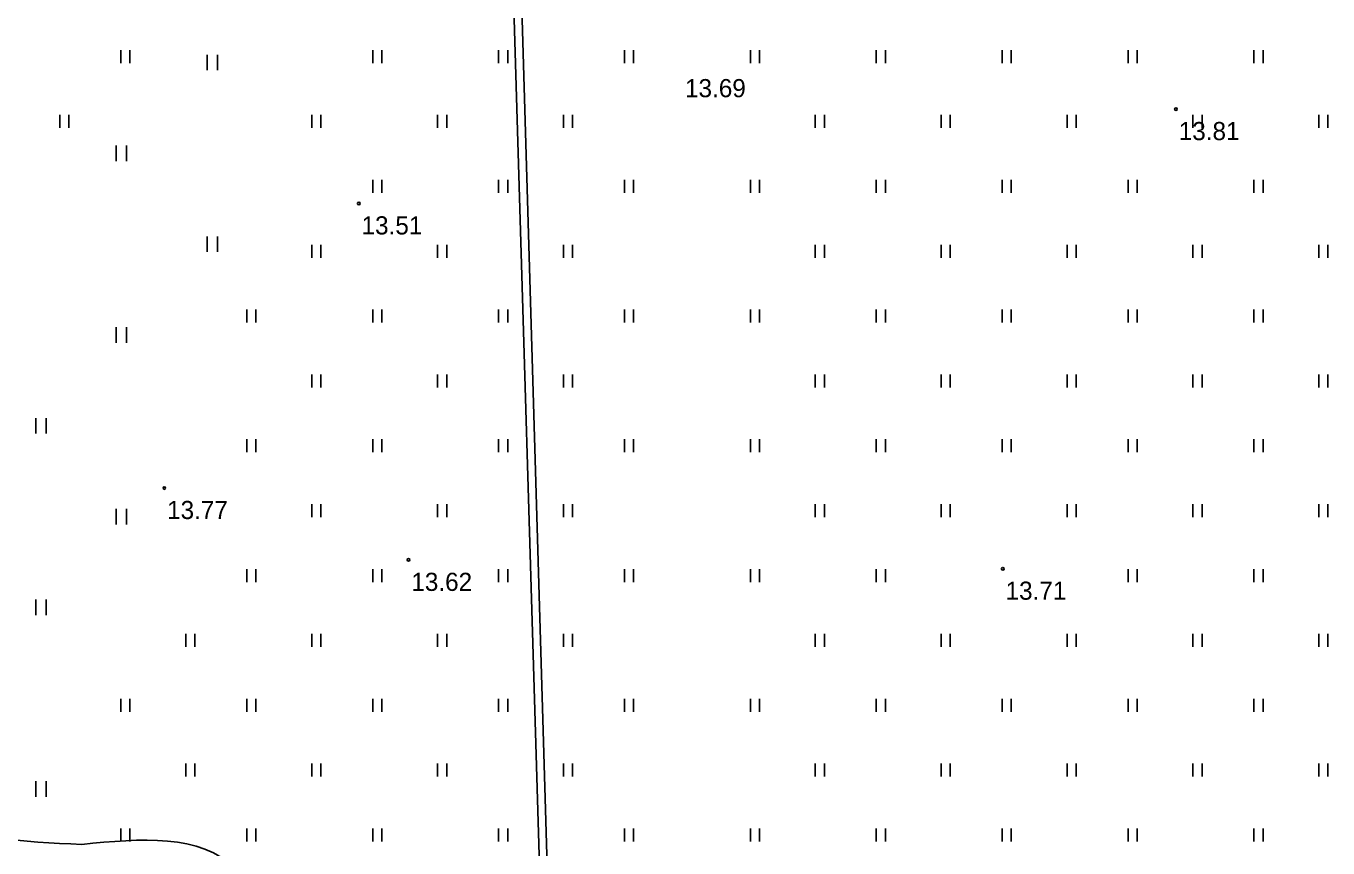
# Model space of a CAD drawing. Extents: x 503877 to 504025, y 304562 to 304725.
# Drawn here: x 503974.7 to 504024.9, y 304658.7 to 304690.4 of the extents above; entities that cross this region are included whole.
import ezdxf

# ---------------------------------------------------------------- set-up
doc = ezdxf.new("R2010")
doc.units = 0
for name, color, linetype in [('CELI_CMAL_####_####_#', 7, 'Continuous'), ('RELJ_AATZ_####_TKST_#', 7, 'Continuous'), ('RELJ_ELEM_####_####_#', 7, 'Continuous'), ('RELJ_HORZ_PAMT_####_#', 7, 'Continuous'), ('SAKT_VADP_KABE_####_#', 7, 'Continuous'), ('TERT_ELEM_####_####_#', 7, 'Continuous')]:
    doc.layers.add(name, color=color, linetype=linetype)

msp = doc.modelspace()

# ---------------------------------------------------------------- linework, layer by layer
at = {"layer": 'CELI_CMAL_####_####_#'}
msp.add_spline([(503958.742, 304680.69), (503969.414, 304697.055), (503975.45, 304710.561), (503980.58, 304721.12)], degree=3, dxfattribs=at)
at = {"layer": 'RELJ_ELEM_####_####_#'}
for centre in [(504019.004, 304687.166), (503987.523, 304683.531), (503980.032, 304672.563), (503989.441, 304669.793), (504012.333, 304669.452)]:
    msp.add_circle(centre, 0.05, dxfattribs=at)
at = {"layer": 'RELJ_HORZ_PAMT_####_#'}
for points in [[(503976.857, 304658.83), (503971.294, 304660.253), (503970.34, 304666.569), (503970.027, 304667.82)], [(503987.539, 304625.902), (503985.892, 304637.275), (503983.106, 304645.98), (503983.425, 304657.056), (503982.792, 304657.882), (503976.857, 304658.83)]]:
    msp.add_spline(points, degree=3, dxfattribs=at)
at = {"layer": 'SAKT_VADP_KABE_####_#'}
for p, q in [((503993.253, 304709.476), (503996.275, 304607.968)), ((503992.977, 304708.659), (503995.977, 304607.917))]:
    msp.add_line(p, q, dxfattribs=at)
at = {"layer": 'TERT_ELEM_####_####_#'}
for p, q in [((503978.36, 304688.941), (503978.36, 304689.441)), ((503978.71, 304688.941), (503978.71, 304689.441)), ((503981.679, 304688.662), (503981.679, 304689.262)), ((503982.079, 304688.662), (503982.079, 304689.262)), ((503988.06, 304688.941), (503988.06, 304689.441)), ((503988.41, 304688.941), (503988.41, 304689.441)), ((503992.91, 304688.941), (503992.91, 304689.441)), ((503993.26, 304688.941), (503993.26, 304689.441)), ((503997.76, 304688.941), (503997.76, 304689.441)), ((503998.11, 304688.941), (503998.11, 304689.441)), ((504002.61, 304688.941), (504002.61, 304689.441)), ((504002.96, 304688.941), (504002.96, 304689.441)), ((504007.46, 304688.941), (504007.46, 304689.441)), ((504007.81, 304688.941), (504007.81, 304689.441)), ((504012.31, 304688.941), (504012.31, 304689.441)), ((504012.66, 304688.941), (504012.66, 304689.441)), ((504017.16, 304688.941), (504017.16, 304689.441)), ((504017.51, 304688.941), (504017.51, 304689.441)), ((504022.01, 304688.941), (504022.01, 304689.441)), ((504022.36, 304688.941), (504022.36, 304689.441)), ((503976.01, 304686.441), (503976.01, 304686.941)), ((503976.36, 304686.441), (503976.36, 304686.941)), ((503985.71, 304686.441), (503985.71, 304686.941)), ((503986.06, 304686.441), (503986.06, 304686.941)), ((503990.56, 304686.441), (503990.56, 304686.941)), ((503990.91, 304686.441), (503990.91, 304686.941)), ((503995.41, 304686.441), (503995.41, 304686.941)), ((503995.76, 304686.441), (503995.76, 304686.941)), ((504005.11, 304686.441), (504005.11, 304686.941)), ((504005.46, 304686.441), (504005.46, 304686.941)), ((504009.96, 304686.441), (504009.96, 304686.941)), ((504010.31, 304686.441), (504010.31, 304686.941)), ((504014.81, 304686.441), (504014.81, 304686.941)), ((504015.16, 304686.441), (504015.16, 304686.941)), ((504019.66, 304686.441), (504019.66, 304686.941)), ((504020.01, 304686.441), (504020.01, 304686.941)), ((504024.51, 304686.441), (504024.51, 304686.941)), ((504024.86, 304686.441), (504024.86, 304686.941)), ((503978.179, 304685.162), (503978.179, 304685.762)), ((503978.579, 304685.162), (503978.579, 304685.762)), ((503988.06, 304683.941), (503988.06, 304684.441)), ((503988.41, 304683.941), (503988.41, 304684.441)), ((503992.91, 304683.941), (503992.91, 304684.441)), ((503993.26, 304683.941), (503993.26, 304684.441)), ((503997.76, 304683.941), (503997.76, 304684.441)), ((503998.11, 304683.941), (503998.11, 304684.441)), ((504002.61, 304683.941), (504002.61, 304684.441)), ((504002.96, 304683.941), (504002.96, 304684.441)), ((504007.46, 304683.941), (504007.46, 304684.441)), ((504007.81, 304683.941), (504007.81, 304684.441)), ((504012.31, 304683.941), (504012.31, 304684.441)), ((504012.66, 304683.941), (504012.66, 304684.441)), ((504017.16, 304683.941), (504017.16, 304684.441)), ((504017.51, 304683.941), (504017.51, 304684.441)), ((504022.01, 304683.941), (504022.01, 304684.441)), ((504022.36, 304683.941), (504022.36, 304684.441)), ((503981.679, 304681.662), (503981.679, 304682.262)), ((503982.079, 304681.662), (503982.079, 304682.262)), ((503985.71, 304681.441), (503985.71, 304681.941)), ((503986.06, 304681.441), (503986.06, 304681.941)), ((503990.56, 304681.441), (503990.56, 304681.941)), ((503990.91, 304681.441), (503990.91, 304681.941)), ((503995.41, 304681.441), (503995.41, 304681.941)), ((503995.76, 304681.441), (503995.76, 304681.941)), ((504005.11, 304681.441), (504005.11, 304681.941)), ((504005.46, 304681.441), (504005.46, 304681.941)), ((504009.96, 304681.441), (504009.96, 304681.941)), ((504010.31, 304681.441), (504010.31, 304681.941)), ((504014.81, 304681.441), (504014.81, 304681.941)), ((504015.16, 304681.441), (504015.16, 304681.941)), ((504019.66, 304681.441), (504019.66, 304681.941)), ((504020.01, 304681.441), (504020.01, 304681.941)), ((504024.51, 304681.441), (504024.51, 304681.941)), ((504024.86, 304681.441), (504024.86, 304681.941)), ((503983.21, 304678.941), (503983.21, 304679.441)), ((503983.56, 304678.941), (503983.56, 304679.441)), ((503988.06, 304678.941), (503988.06, 304679.441)), ((503988.41, 304678.941), (503988.41, 304679.441)), ((503992.91, 304678.941), (503992.91, 304679.441)), ((503993.26, 304678.941), (503993.26, 304679.441)), ((503997.76, 304678.941), (503997.76, 304679.441)), ((503998.11, 304678.941), (503998.11, 304679.441)), ((504002.61, 304678.941), (504002.61, 304679.441)), ((504002.96, 304678.941), (504002.96, 304679.441)), ((504007.46, 304678.941), (504007.46, 304679.441)), ((504007.81, 304678.941), (504007.81, 304679.441)), ((504012.31, 304678.941), (504012.31, 304679.441)), ((504012.66, 304678.941), (504012.66, 304679.441)), ((504017.16, 304678.941), (504017.16, 304679.441)), ((504017.51, 304678.941), (504017.51, 304679.441)), ((504022.01, 304678.941), (504022.01, 304679.441)), ((504022.36, 304678.941), (504022.36, 304679.441)), ((503978.179, 304678.162), (503978.179, 304678.762)), ((503978.579, 304678.162), (503978.579, 304678.762)), ((503985.71, 304676.441), (503985.71, 304676.941)), ((503986.06, 304676.441), (503986.06, 304676.941)), ((503990.56, 304676.441), (503990.56, 304676.941)), ((503990.91, 304676.441), (503990.91, 304676.941)), ((503995.41, 304676.441), (503995.41, 304676.941)), ((503995.76, 304676.441), (503995.76, 304676.941)), ((504005.11, 304676.441), (504005.11, 304676.941)), ((504005.46, 304676.441), (504005.46, 304676.941)), ((504009.96, 304676.441), (504009.96, 304676.941)), ((504010.31, 304676.441), (504010.31, 304676.941)), ((504014.81, 304676.441), (504014.81, 304676.941)), ((504015.16, 304676.441), (504015.16, 304676.941)), ((504019.66, 304676.441), (504019.66, 304676.941)), ((504020.01, 304676.441), (504020.01, 304676.941)), ((504024.51, 304676.441), (504024.51, 304676.941)), ((504024.86, 304676.441), (504024.86, 304676.941)), ((503975.079, 304674.662), (503975.079, 304675.262)), ((503975.479, 304674.662), (503975.479, 304675.262)), ((503983.21, 304673.941), (503983.21, 304674.441)), ((503983.56, 304673.941), (503983.56, 304674.441)), ((503988.06, 304673.941), (503988.06, 304674.441)), ((503988.41, 304673.941), (503988.41, 304674.441)), ((503992.91, 304673.941), (503992.91, 304674.441)), ((503993.26, 304673.941), (503993.26, 304674.441)), ((503997.76, 304673.941), (503997.76, 304674.441)), ((503998.11, 304673.941), (503998.11, 304674.441)), ((504002.61, 304673.941), (504002.61, 304674.441)), ((504002.96, 304673.941), (504002.96, 304674.441)), ((504007.46, 304673.941), (504007.46, 304674.441)), ((504007.81, 304673.941), (504007.81, 304674.441)), ((504012.31, 304673.941), (504012.31, 304674.441)), ((504012.66, 304673.941), (504012.66, 304674.441)), ((504017.16, 304673.941), (504017.16, 304674.441)), ((504017.51, 304673.941), (504017.51, 304674.441)), ((504022.01, 304673.941), (504022.01, 304674.441)), ((504022.36, 304673.941), (504022.36, 304674.441)), ((503978.179, 304671.162), (503978.179, 304671.762)), ((503978.579, 304671.162), (503978.579, 304671.762)), ((503985.71, 304671.441), (503985.71, 304671.941)), ((503986.06, 304671.441), (503986.06, 304671.941)), ((503990.56, 304671.441), (503990.56, 304671.941)), ((503990.91, 304671.441), (503990.91, 304671.941)), ((503995.41, 304671.441), (503995.41, 304671.941)), ((503995.76, 304671.441), (503995.76, 304671.941)), ((504005.11, 304671.441), (504005.11, 304671.941)), ((504005.46, 304671.441), (504005.46, 304671.941)), ((504009.96, 304671.441), (504009.96, 304671.941)), ((504010.31, 304671.441), (504010.31, 304671.941)), ((504014.81, 304671.441), (504014.81, 304671.941)), ((504015.16, 304671.441), (504015.16, 304671.941)), ((504019.66, 304671.441), (504019.66, 304671.941)), ((504020.01, 304671.441), (504020.01, 304671.941)), ((504024.51, 304671.441), (504024.51, 304671.941)), ((504024.86, 304671.441), (504024.86, 304671.941)), ((503983.21, 304668.941), (503983.21, 304669.441)), ((503983.56, 304668.941), (503983.56, 304669.441)), ((503988.06, 304668.941), (503988.06, 304669.441)), ((503988.41, 304668.941), (503988.41, 304669.441)), ((503992.91, 304668.941), (503992.91, 304669.441)), ((503993.26, 304668.941), (503993.26, 304669.441)), ((503997.76, 304668.941), (503997.76, 304669.441)), ((503998.11, 304668.941), (503998.11, 304669.441)), ((504002.61, 304668.941), (504002.61, 304669.441)), ((504002.96, 304668.941), (504002.96, 304669.441)), ((504007.46, 304668.941), (504007.46, 304669.441)), ((504007.81, 304668.941), (504007.81, 304669.441)), ((504017.16, 304668.941), (504017.16, 304669.441)), ((504017.51, 304668.941), (504017.51, 304669.441)), ((504022.01, 304668.941), (504022.01, 304669.441)), ((504022.36, 304668.941), (504022.36, 304669.441)), ((503975.079, 304667.662), (503975.079, 304668.262)), ((503975.479, 304667.662), (503975.479, 304668.262)), ((503980.86, 304666.441), (503980.86, 304666.941)), ((503981.21, 304666.441), (503981.21, 304666.941)), ((503985.71, 304666.441), (503985.71, 304666.941)), ((503986.06, 304666.441), (503986.06, 304666.941)), ((503990.56, 304666.441), (503990.56, 304666.941)), ((503990.91, 304666.441), (503990.91, 304666.941)), ((503995.41, 304666.441), (503995.41, 304666.941)), ((503995.76, 304666.441), (503995.76, 304666.941)), ((504005.11, 304666.441), (504005.11, 304666.941)), ((504005.46, 304666.441), (504005.46, 304666.941)), ((504009.96, 304666.441), (504009.96, 304666.941)), ((504010.31, 304666.441), (504010.31, 304666.941)), ((504014.81, 304666.441), (504014.81, 304666.941)), ((504015.16, 304666.441), (504015.16, 304666.941)), ((504019.66, 304666.441), (504019.66, 304666.941)), ((504020.01, 304666.441), (504020.01, 304666.941)), ((504024.51, 304666.441), (504024.51, 304666.941)), ((504024.86, 304666.441), (504024.86, 304666.941)), ((503978.36, 304663.941), (503978.36, 304664.441)), ((503978.71, 304663.941), (503978.71, 304664.441)), ((503983.21, 304663.941), (503983.21, 304664.441)), ((503983.56, 304663.941), (503983.56, 304664.441)), ((503988.06, 304663.941), (503988.06, 304664.441)), ((503988.41, 304663.941), (503988.41, 304664.441)), ((503992.91, 304663.941), (503992.91, 304664.441)), ((503993.26, 304663.941), (503993.26, 304664.441)), ((503997.76, 304663.941), (503997.76, 304664.441)), ((503998.11, 304663.941), (503998.11, 304664.441)), ((504002.61, 304663.941), (504002.61, 304664.441)), ((504002.96, 304663.941), (504002.96, 304664.441)), ((504007.46, 304663.941), (504007.46, 304664.441)), ((504007.81, 304663.941), (504007.81, 304664.441)), ((504012.31, 304663.941), (504012.31, 304664.441)), ((504012.66, 304663.941), (504012.66, 304664.441)), ((504017.16, 304663.941), (504017.16, 304664.441)), ((504017.51, 304663.941), (504017.51, 304664.441)), ((504022.01, 304663.941), (504022.01, 304664.441)), ((504022.36, 304663.941), (504022.36, 304664.441)), ((503980.86, 304661.441), (503980.86, 304661.941)), ((503981.21, 304661.441), (503981.21, 304661.941)), ((503985.71, 304661.441), (503985.71, 304661.941)), ((503986.06, 304661.441), (503986.06, 304661.941)), ((503990.56, 304661.441), (503990.56, 304661.941)), ((503990.91, 304661.441), (503990.91, 304661.941)), ((503995.41, 304661.441), (503995.41, 304661.941)), ((503995.76, 304661.441), (503995.76, 304661.941)), ((504005.11, 304661.441), (504005.11, 304661.941)), ((504005.46, 304661.441), (504005.46, 304661.941)), ((504009.96, 304661.441), (504009.96, 304661.941)), ((504010.31, 304661.441), (504010.31, 304661.941)), ((504014.81, 304661.441), (504014.81, 304661.941)), ((504015.16, 304661.441), (504015.16, 304661.941)), ((504019.66, 304661.441), (504019.66, 304661.941)), ((504020.01, 304661.441), (504020.01, 304661.941)), ((504024.51, 304661.441), (504024.51, 304661.941)), ((504024.86, 304661.441), (504024.86, 304661.941)), ((503975.079, 304660.662), (503975.079, 304661.262)), ((503975.479, 304660.662), (503975.479, 304661.262)), ((503978.36, 304658.941), (503978.36, 304659.441)), ((503978.71, 304658.941), (503978.71, 304659.441)), ((503983.21, 304658.941), (503983.21, 304659.441)), ((503983.56, 304658.941), (503983.56, 304659.441)), ((503988.06, 304658.941), (503988.06, 304659.441)), ((503988.41, 304658.941), (503988.41, 304659.441)), ((503992.91, 304658.941), (503992.91, 304659.441)), ((503993.26, 304658.941), (503993.26, 304659.441)), ((503997.76, 304658.941), (503997.76, 304659.441)), ((503998.11, 304658.941), (503998.11, 304659.441)), ((504002.61, 304658.941), (504002.61, 304659.441)), ((504002.96, 304658.941), (504002.96, 304659.441)), ((504007.46, 304658.941), (504007.46, 304659.441)), ((504007.81, 304658.941), (504007.81, 304659.441)), ((504012.31, 304658.941), (504012.31, 304659.441)), ((504012.66, 304658.941), (504012.66, 304659.441)), ((504017.16, 304658.941), (504017.16, 304659.441)), ((504017.51, 304658.941), (504017.51, 304659.441)), ((504022.01, 304658.941), (504022.01, 304659.441)), ((504022.36, 304658.941), (504022.36, 304659.441))]:
    msp.add_line(p, q, dxfattribs=at)

# ---------------------------------------------------------------- texts
at = {"layer": 'RELJ_AATZ_####_TKST_#'}
for s, p in [('13.69', (504000.091, 304687.624)), ('13.81', (504019.111, 304685.971)), ('13.51', (503987.63, 304682.336)), ('13.77', (503980.139, 304671.368)), ('13.62', (503989.548, 304668.598)), ('13.71', (504012.44, 304668.258))]:
    msp.add_text(s, height=0.7, dxfattribs=at).set_placement(p)

doc.saveas('drawing.dxf')
